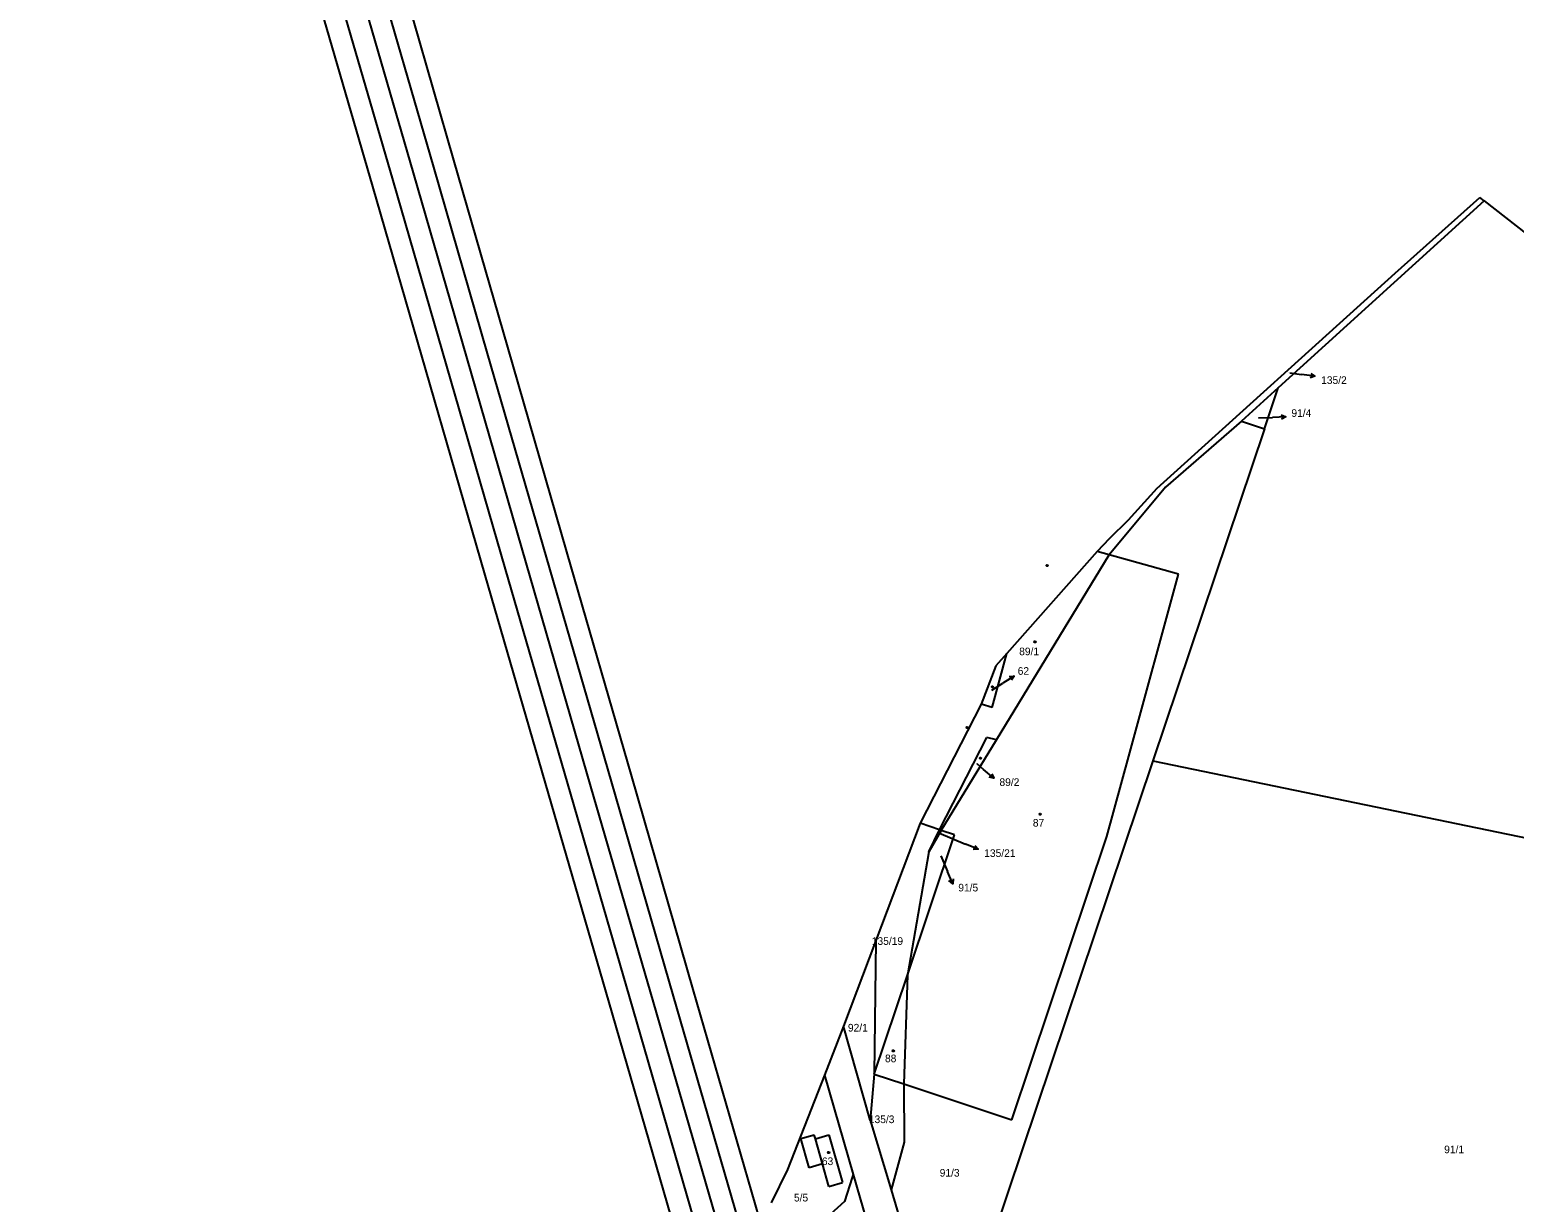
# Model space of a CAD drawing. Extents: x -752343 to -750336, y -1035826 to -1033329.
# Drawn here: x -751924.2 to -751593.9, y -1033871.2 to -1033610.5 of the extents above; entities that cross this region are included whole.
import ezdxf

# ---------------------------------------------------------------- set-up
doc = ezdxf.new("R2010")
doc.units = 0
for name, color, linetype in [('Default', 7, 'Continuous'), ('KN_HRANICE', 7, 'Continuous'), ('KN_KULTURY', 7, 'Continuous'), ('KN_PARCELY', 7, 'Continuous'), ('KN_SLUCKY', 7, 'Continuous'), ('Vrstva 1', 7, 'Continuous')]:
    doc.layers.add(name, color=color, linetype=linetype)

# ---------------------------------------------------------------- blocks, each defined once
blk = doc.blocks.new('10292')
at = {"layer": 'Default'}
blk.add_line((0, 3), (0, 0), dxfattribs=at)
blk.add_lwpolyline([(-0.5, 2), (0, 3), (0.5, 2)], dxfattribs=at)
blk = doc.blocks.new('402')
at = {"layer": 'Default'}
blk.add_lwpolyline([(0.09, 0.15), (0.18, 0), (0.09, -0.15), (-0.09, -0.15), (-0.18, 0), (-0.09, 0.15), (0.09, 0.15)], dxfattribs=at)

msp = doc.modelspace()

# ---------------------------------------------------------------- linework, layer by layer
at = {"layer": 'KN_HRANICE'}
for p, q in [((-751600.62, -1033648.57), (-751646.41, -1033690.12)), ((-751620.38, -1033664.69), (-751601.61, -1033647.82)), ((-751600.62, -1033648.57), (-751601.61, -1033647.82)), ((-751600.62, -1033648.57), (-751579.75, -1033664.94)), ((-751673.42, -1033712.57), (-751620.38, -1033664.69)), ((-751646.41, -1033690.12), (-751654.62, -1033697.57)), ((-751649.5, -1033699.28), (-751646.41, -1033690.12)), ((-751654.62, -1033697.57), (-751671.51, -1033712.21)), ((-751654.62, -1033697.57), (-751649.5, -1033699.28)), ((-751649.5, -1033699.28), (-751674.33, -1033773.12)), ((-751671.51, -1033712.21), (-751684.01, -1033727.32)), ((-751673.42, -1033712.57), (-751679.83, -1033719.58)), ((-751679.83, -1033719.58), (-751684.07, -1033723.74)), ((-751684.07, -1033723.74), (-751686.7, -1033726.57)), ((-751709.08, -1033768.39), (-751684.01, -1033727.32)), ((-751686.7, -1033726.57), (-751706.79, -1033749.21)), ((-751684.01, -1033727.32), (-751686.7, -1033726.57)), ((-751668.6, -1033731.57), (-751684.01, -1033727.32)), ((-751679.67, -1033772.02), (-751668.6, -1033731.57)), ((-751710.08, -1033761.2), (-751706.79, -1033749.21)), ((-751706.79, -1033749.21), (-751709.24, -1033751.97)), ((-751709.24, -1033751.97), (-751712.49, -1033760.52)), ((-751712.49, -1033760.52), (-751726.1, -1033786.95)), ((-751710.08, -1033761.2), (-751712.49, -1033760.52)), ((-751721.77, -1033788.42), (-751711.24, -1033767.89)), ((-751709.08, -1033768.39), (-751711.24, -1033767.89)), ((-751721.39, -1033788.55), (-751709.08, -1033768.39)), ((-751674.33, -1033773.12), (-751714, -1033891.06)), ((-751684.56, -1033789.88), (-751679.67, -1033772.02)), ((-751674.33, -1033773.12), (-751500.87, -1033808.86)), ((-751726.1, -1033786.95), (-751735.93, -1033813.02)), ((-751721.77, -1033788.42), (-751726.1, -1033786.95)), ((-751728.9, -1033820.71), (-751718.44, -1033789.55)), ((-751724.13, -1033793.3), (-751721.77, -1033788.42)), ((-751721.39, -1033788.55), (-751724.13, -1033793.3)), ((-751721.39, -1033788.55), (-751721.77, -1033788.42)), ((-751718.44, -1033789.55), (-751721.39, -1033788.55)), ((-751705.73, -1033852.93), (-751684.56, -1033789.88)), ((-751724.13, -1033793.3), (-751728.9, -1033820.71)), ((-751735.93, -1033813.02), (-751743.12, -1033832.07)), ((-751735.93, -1033813.02), (-751736.29, -1033842.73)), ((-751736.29, -1033842.73), (-751728.9, -1033820.71)), ((-751728.9, -1033820.71), (-751729.71, -1033844.93)), ((-751743.12, -1033832.07), (-751747.38, -1033842.95)), ((-751737.18, -1033852.97), (-751743.12, -1033832.07)), ((-751747.38, -1033842.95), (-751755.6, -1033863.97)), ((-751747.38, -1033842.95), (-751740.99, -1033865.03)), ((-751736.29, -1033842.73), (-751737.18, -1033852.97)), ((-751736.29, -1033842.73), (-751729.71, -1033844.93)), ((-751729.71, -1033844.93), (-751705.73, -1033852.93)), ((-751729.71, -1033844.93), (-751729.68, -1033857.86)), ((-751737.18, -1033852.97), (-751732.54, -1033868.49)), ((-751752.63, -1033857.07), (-751749.65, -1033856.23)), ((-751750.79, -1033863.54), (-751752.63, -1033857.07)), ((-751749.4, -1033857.1), (-751749.65, -1033856.23)), ((-751749.4, -1033857.1), (-751746.42, -1033856.24)), ((-751746.42, -1033856.24), (-751743.33, -1033866.83)), ((-751729.68, -1033857.86), (-751732.54, -1033868.49)), ((-751755.6, -1033863.97), (-751759.23, -1033871.39)), ((-751747.81, -1033862.69), (-751750.79, -1033863.54)), ((-751746.39, -1033867.7), (-751747.81, -1033862.69)), ((-751746.39, -1033867.7), (-751743.33, -1033866.83)), ((-751741.21, -1033865.7), (-751742.93, -1033871.04)), ((-751740.99, -1033865.03), (-751741.21, -1033865.7)), ((-751740.99, -1033865.03), (-751737.37, -1033877.6)), ((-751732.54, -1033868.49), (-751726.47, -1033888.81)), ((-751742.93, -1033871.04), (-751748.35, -1033875.98))]:
    msp.add_line(p, q, dxfattribs=at)
at = {"layer": 'KN_PARCELY'}
for p, q in [((-751643.86, -1033686.85), (-751641.24, -1033687.2)), ((-751650.8, -1033696.84), (-751647.74, -1033696.72)), ((-751710.11, -1033757.35), (-751707.7, -1033755.83)), ((-751713.49, -1033773.7), (-751711.96, -1033775.02)), ((-751721.93, -1033789.08), (-751715.98, -1033791.59)), ((-751721.47, -1033794.19), (-751720.01, -1033797.66))]:
    msp.add_line(p, q, dxfattribs=at)
at = {"layer": 'KN_SLUCKY'}
msp.add_line((-751747.81, -1033862.69), (-751749.4, -1033857.1), dxfattribs=at)
at = {"layer": 'Vrstva 1'}
for points in [[(-751747.7, -1033990.96), (-751752.23, -1033975.31), (-751766.26, -1033926.94), (-751779.77, -1033880.3), (-751794.62, -1033829.08), (-751808.74, -1033780.36), (-751822.83, -1033731.78), (-751836.05, -1033686.18), (-751847.86, -1033645.42), (-751861.7, -1033597.67), (-751876.18, -1033547.72), (-751888.67, -1033504.63), (-751900.66, -1033463.43), (-751906.4, -1033443.73), (-751912.15, -1033423.91), (-751917.69, -1033403.66), (-751919.57, -1033395.91), (-751922, -1033384.17), (-751924.19, -1033371.37)], [(-751747.25, -1033975.4), (-751747.77, -1033973.62), (-751761.05, -1033927.91), (-751775.46, -1033878.23), (-751789.94, -1033828.29), (-751803.8, -1033780.5), (-751818.3, -1033730.5), (-751831.4, -1033685.33), (-751843.36, -1033644.03), (-751857.18, -1033596.38), (-751871.7, -1033546.26), (-751884.52, -1033502.07), (-751896.51, -1033460.66), (-751904.76, -1033432.15), (-751912.03, -1033407.03)], [(-751742.63, -1033974.06), (-751743.25, -1033971.96), (-751756.5, -1033926.32), (-751770.85, -1033876.86), (-751785.4, -1033826.74), (-751799.32, -1033778.78), (-751813.72, -1033729.09), (-751826.88, -1033683.61), (-751838.83, -1033642.34), (-751852.51, -1033595.07), (-751867.05, -1033544.93), (-751874.95, -1033517.68), (-751883.31, -1033488.69), (-751888.73, -1033469.92), (-751892.18, -1033457.94), (-751895.7, -1033445.91)], [(-751748.37, -1033937.64), (-751749.35, -1033934.24), (-751752.08, -1033924.85), (-751766.48, -1033875.28), (-751780.94, -1033825.44), (-751794.79, -1033777.71), (-751809.23, -1033727.82), (-751822.32, -1033682.55), (-751834.31, -1033641.08), (-751848, -1033593.76), (-751862.53, -1033543.58), (-751870.21, -1033516.87), (-751874.49, -1033501.96), (-751877.86, -1033490.12), (-751881.3, -1033478.36)], [(-751744.43, -1033936.13), (-751747.53, -1033924.25), (-751761.89, -1033874.59), (-751776.58, -1033823.89), (-751790.24, -1033776.6), (-751804.68, -1033726.65), (-751817.84, -1033681.12), (-751829.8, -1033639.54), (-751843.42, -1033592.34), (-751857.99, -1033542.2), (-751866.58, -1033512.39), (-751871.08, -1033498.48), (-751874.93, -1033488.43), (-751879.76, -1033477.74)]]:
    msp.add_lwpolyline(points, dxfattribs=at)

# ---------------------------------------------------------------- block references
at = {"layer": 'KN_KULTURY'}
for p in [(-751697.84, -1033729.63), (-751700.54, -1033746.62), (-751710.01, -1033756.6), (-751715.62, -1033765.65), (-751712.68, -1033772.47), (-751699.39, -1033784.95), (-751732.07, -1033837.54), (-751746.45, -1033860.17)]:
    msp.add_blockref('402', p, dxfattribs=at)
at = {"layer": 'KN_PARCELY'}
for p, rotation in [((-751641.24, -1033687.2), -97.52803400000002), ((-751647.74, -1033696.72), -87.84504700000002), ((-751707.7, -1033755.83), -57.650172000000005), ((-751711.96, -1033775.02), -130.644995), ((-751715.98, -1033791.59), -112.82600699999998), ((-751720.01, -1033797.66), -157.115645)]:
    msp.add_blockref('10292', p, dxfattribs=dict(at, rotation=rotation))

# ---------------------------------------------------------------- texts
for s, height, p in [('135/2', 0.1, (-751644.11, -1033686.85)), ('135/2', 1.7, (-751636.88, -1033689.29)), ('91/4', 1.7, (-751643.5, -1033696.61)), ('91/4', 0.1, (-751651, -1033696.84)), ('89/1', 1.7, (-751704.06, -1033749.61)), ('62', 1.7, (-751704.39, -1033753.96)), ('62', 0.1, (-751710.21, -1033757.35)), ('89/2', 0.1, (-751713.69, -1033773.7)), ('89/2', 1.7, (-751708.44, -1033778.67)), ('87', 1.7, (-751701.02, -1033787.71)), ('91/5', 0.1, (-751721.67, -1033794.19)), ('135/21', 1.7, (-751711.83, -1033794.45)), ('91/5', 1.7, (-751717.6, -1033802.12)), ('135/19', 1.7, (-751736.84, -1033814)), ('92/1', 1.7, (-751742.16, -1033833.27)), ('88', 1.7, (-751733.91, -1033840.09)), ('135/3', 1.7, (-751737.5, -1033853.63)), ('91/1', 1.7, (-751609.51, -1033860.33)), ('63', 1.7, (-751747.95, -1033862.96)), ('91/3', 1.7, (-751721.74, -1033865.52)), ('5/5', 1.7, (-751754.16, -1033871.05))]:
    msp.add_text(s, height=height, dxfattribs=at).set_placement(p)
msp.add_text('135/21', height=0.1, rotation=61.879, dxfattribs=at).set_placement((-751721.86, -1033789.09))

doc.saveas('drawing.dxf')
